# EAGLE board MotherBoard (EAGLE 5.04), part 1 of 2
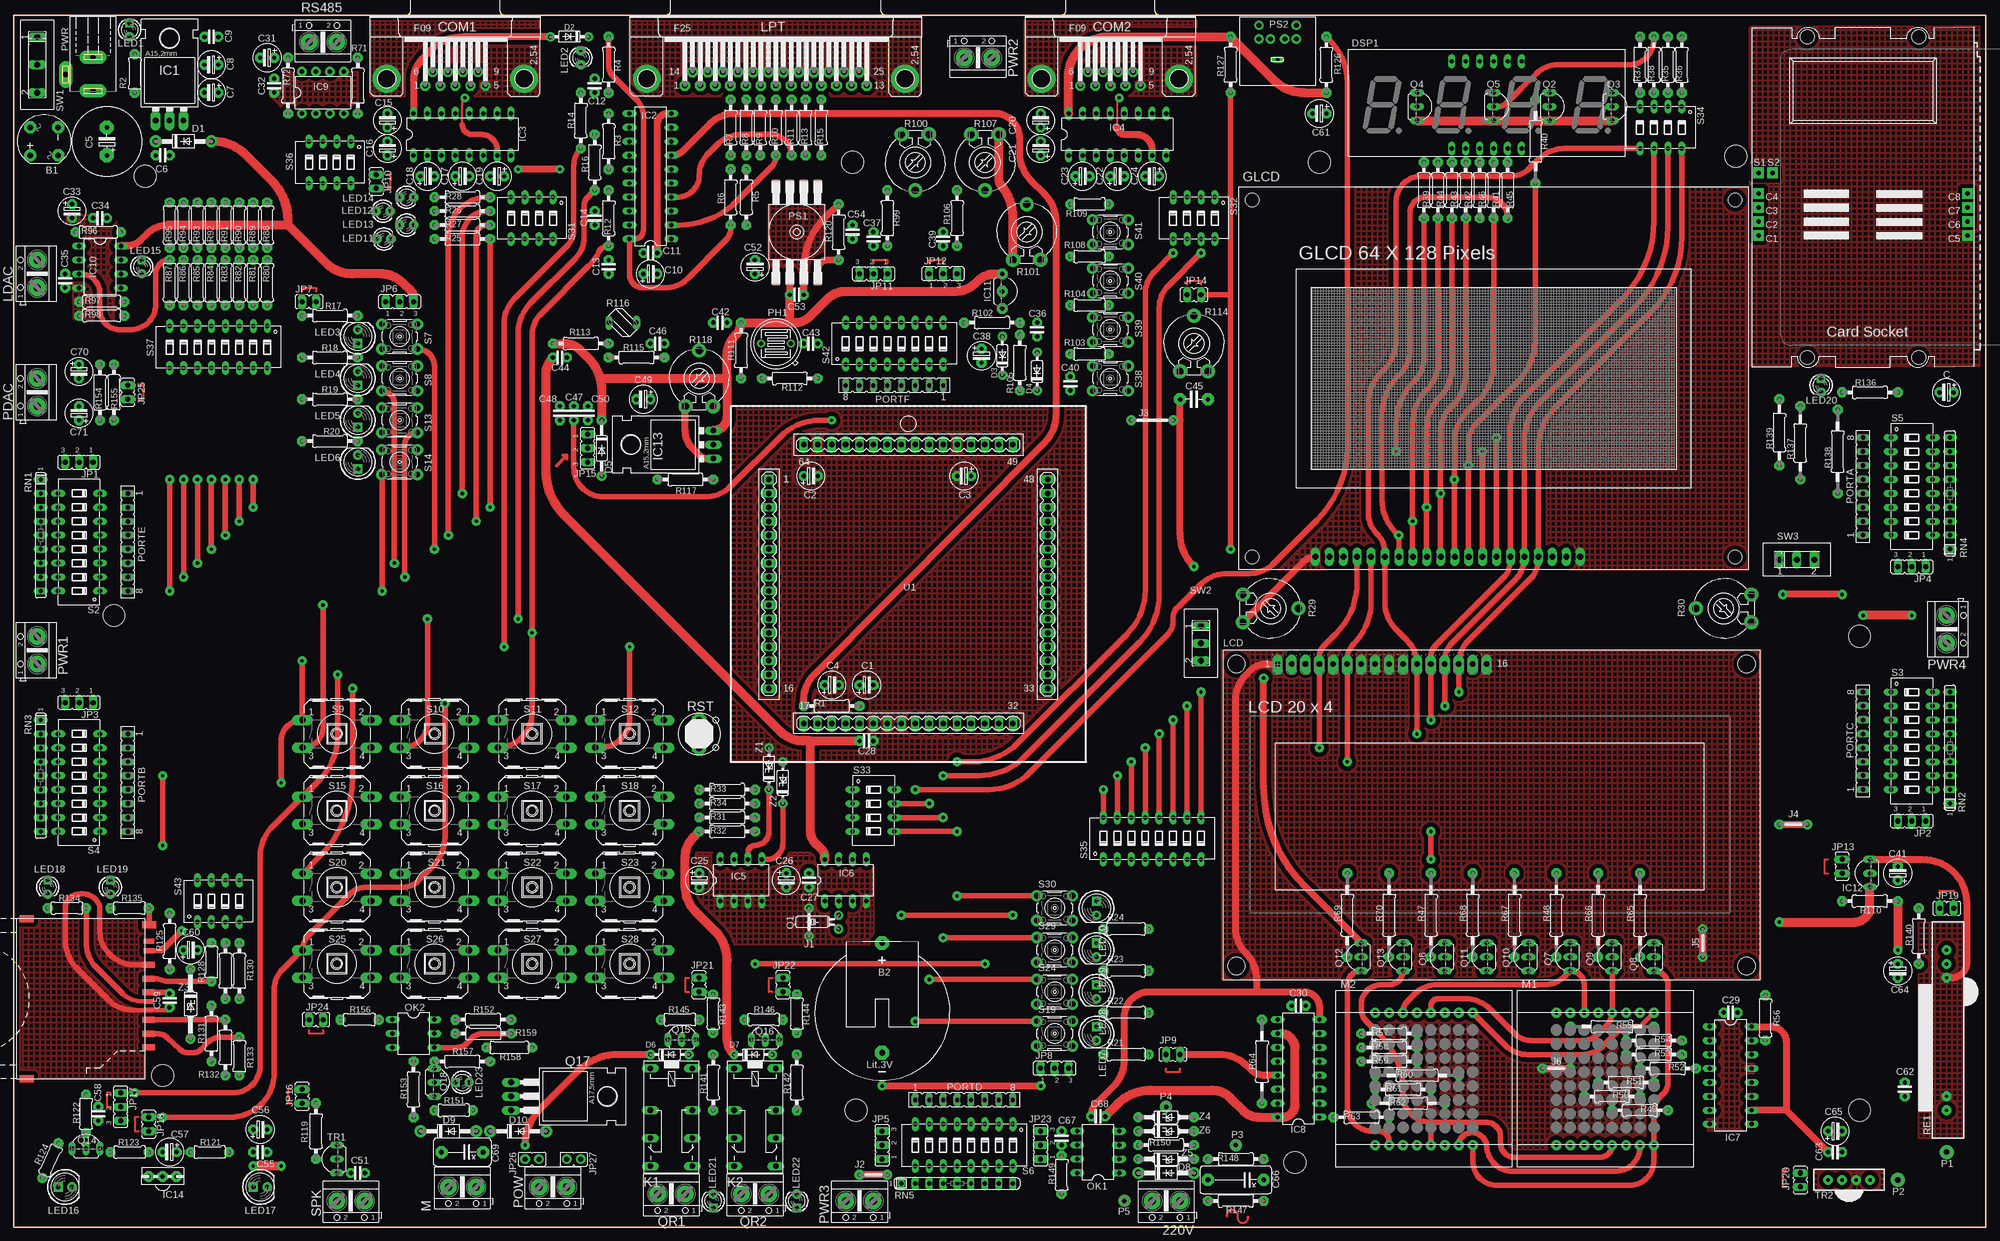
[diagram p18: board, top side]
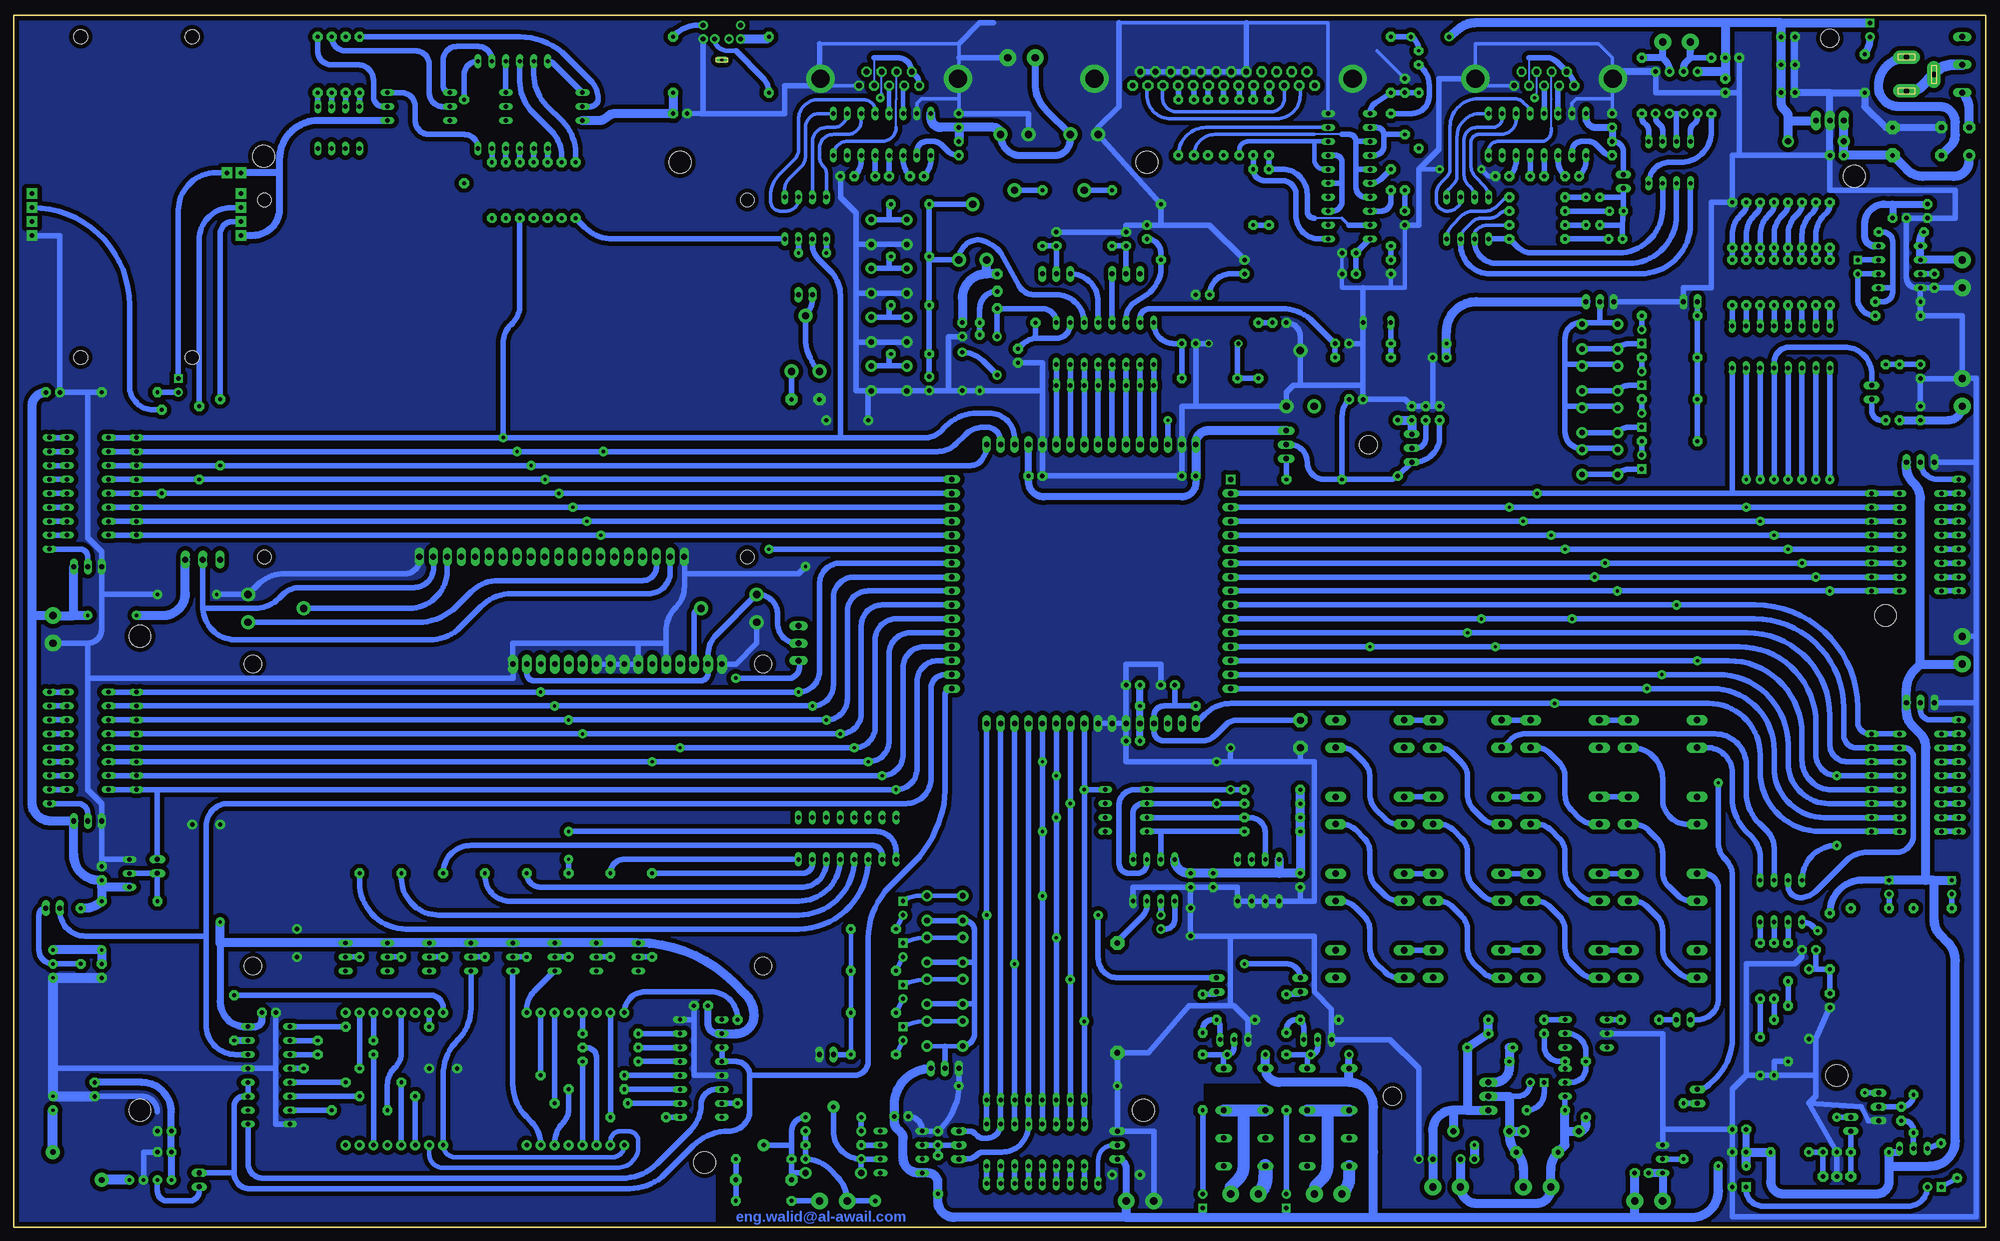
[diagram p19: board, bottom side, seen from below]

Size 359.41 x 220.82 mm. Coordinates in mm from the lower left corner, seen from the top.
Outline: 0.01,220.81 0.01,0.01
Outline: 0,0 359.41,0 359.41,220.82 0,220.82
Copper layers (1*16): Top 0.035mm / dielectric 1.5mm / Bottom 0.035mm
Design rules "default *": minimum track width 32mil, minimum drill 20mil, track to track 8mil, track to pad 8mil, pad to pad 8mil, via to via 8mil, smd to smd 8mil, copper to edge 20mil, drill to drill 8mil, minimum pad ring 10mil, minimum via ring 8mil, stop-mask expansion 4mil, vias tented up to drill 0mil, thermal gap 10mil
Holes 4 mm at 336.39,21.27 336.39,107.63 27.15,27.62 23.97,191.45 18.26,111.44 313.85,195.1 153.51,21.27 233.52,11.75 237.97,193.99 152.88,193.99

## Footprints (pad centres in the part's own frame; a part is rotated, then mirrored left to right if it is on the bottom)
AK500/2 = drill 1.321 pad 3.048 round: 1 -2.515,0; 2 2.515,0
RB1A = drill 1.016 pad 2.184 round: + -2.54,2.54 | drill 1.016 pad 2.184 octagon: - 2.54,-2.54; AC1 2.54,2.54; AC2 -2.54,-2.54
BATT = drill 1.016 pad 2.54 octagon: + 0,10.16; - 0,-9.842
ELC2.5 = drill 0.8 pad 1.778 octagon: 1 -1.27,0; 2 1.27,0
ELC5 = drill 0.8 pad 2.54 octagon: 1 -2.54,0; 2 2.54,0
CAP2.5 = drill 0.8 pad 1.778 octagon: 1 -1.27,0; 2 1.27,0
CAP5 = drill 0.8 pad 2.184 octagon: 1 -2.54,0; 2 2.54,0
CXXC10BS = drill 0.9 pad 2.184 octagon: 1 -5.08,0; 2 5.08,0
CXXC7BS = drill 0.9 pad 2.184 octagon: 1 -5.08,0; 2 2.54,0
F09HP = drill 1.016 pad 1.778 octagon: 1 -5.486,-1.27; 2 -2.743,-1.27; 3 0,-1.27; 4 2.743,-1.27; 5 5.486,-1.27; 6 -4.115,1.27; 7 -1.372,1.27; 8 1.372,1.27; 9 4.115,1.27 | drill 3.302 pad 5.08 round: G1 -12.522,0; G2 12.522,0
DO41-10 = drill 1.118 pad 2.184 round: A 5.08,0; C -5.08,0
DO35-7 = drill 0.813 pad 1.676 round: A 3.175,0; C -3.81,0
DO35-10 = drill 0.813 pad 1.778 round: A 5.08,0; C -5.08,0
DISPLAY-Q0.56 = drill 0.813 long: 1 -6.35,-7.62; 2 -3.81,-7.62; 3 -1.27,-7.62; 4 1.27,-7.62; 5 3.81,-7.62; 6 6.35,-7.62; 7 6.35,8.255; 8 3.81,8.255; 9 1.27,8.255; 10 -1.27,8.255; 11 -3.81,8.255; 12 -6.35,8.255
LCD128X64 = drill 1.1 pad 1.676 long: 1 15.76,-32.5; 2 13.22,-32.5; 3 10.68,-32.5; 4 8.14,-32.5; 5 5.6,-32.5; 6 3.06,-32.5; 7 0.52,-32.5; 8 -2.02,-32.5; 9 -4.56,-32.5; 10 -7.1,-32.5; 11 -9.64,-32.5; 12 -12.18,-32.5; 13 -14.72,-32.5; 14 -17.26,-32.5; 15 -19.8,-32.5; 16 -22.34,-32.5; 17 -24.88,-32.5; 18 -27.42,-32.5; 19 -29.96,-32.5; 20 -32.5,-32.5 | hole 2.5: -44,-32.5; 44,-32.5; -44,32.5; 44,32.5
78XXL = drill 1.016 pad 1.778 long: GND 0,-3.81; IN -2.54,-3.81; OUT 2.54,-3.81 | hole 3.302: 0,11.176
DIL20 = drill 0.813 long: 1 -11.43,-3.81; 2 -8.89,-3.81; 3 -6.35,-3.81; 4 -3.81,-3.81; 5 -1.27,-3.81; 6 1.27,-3.81; 7 3.81,-3.81; 8 6.35,-3.81; 9 8.89,-3.81; 10 11.43,-3.81; 11 11.43,3.81; 12 8.89,3.81; 13 6.35,3.81; 14 3.81,3.81; 15 1.27,3.81; 16 -1.27,3.81; 17 -3.81,3.81; 18 -6.35,3.81; 19 -8.89,3.81; 20 -11.43,3.81
DIL16L = drill 0.813 long: 1 -8.89,-3.81; 2 -6.35,-3.81; 3 -3.81,-3.81; 4 -1.27,-3.81; 5 1.27,-3.81; 6 3.81,-3.81; 7 6.35,-3.81; 8 8.89,-3.81; 9 8.89,3.81; 10 6.35,3.81; 11 3.81,3.81; 12 1.27,3.81; 13 -1.27,3.81; 14 -3.81,3.81; 15 -6.35,3.81; 16 -8.89,3.81
DIL8L = drill 0.813 long: 1 -3.81,-3.81; 2 -1.27,-3.81; 3 1.27,-3.81; 4 3.81,-3.81; 5 3.81,3.81; 6 1.27,3.81; 7 -1.27,3.81; 8 -3.81,3.81
DIL8R = drill 0.813 pad 1.778 round: 1 -3.81,-3.81; 2 -1.27,-3.81; 3 1.27,-3.81; 4 3.81,-3.81; 5 3.81,3.81; 6 1.27,3.81; 7 -1.27,3.81; 8 -3.81,3.81
DIL08 = drill 0.813 long: 1 -3.81,-3.81; 2 -1.27,-3.81; 3 1.27,-3.81; 4 3.81,-3.81; 5 3.81,3.81; 6 1.27,3.81; 7 -1.27,3.81; 8 -3.81,3.81
LM35 = drill 0.813 pad 1.93 octagon: 1 3.175,0; 2 0,0; 3 -3.175,0
TO92L = drill 0.813 long: 1 2.54,0; 2 0,0; 3 -2.54,0
317TL = drill 1.016 long: 1 -2.54,-3.81; 2 0,-3.81; 3 2.54,-3.81 | hole 3.302: 0,11.176
IR-RECEIVER = drill 0.813 pad 1.93 octagon: GND 0,0; OUT 2.54,0; VCC -2.54,0
05 = drill 0.813 pad 1.6 octagon: 1 -2.54,0; 2 2.54,0
05' = drill 0.8 pad 1.778 round: 1 -2.54,0; 2 2.54,0
07 = drill 0.8 pad 1.778 round: 1 -3.81,0; 2 3.81,0
JP2 = drill 0.914 long: 1 -2.54,0; 2 0,0; 3 2.54,0
JP1Y = drill 0.914 long: 1 0,-1.27; 2 0,1.27
JP1 = drill 0.914 pad 1.778 round: 1 0,-1.27; 2 0,1.27
351 = drill 1.016 long: 1 -3.81,-3.81; 16 -3.81,3.81; O1 8.89,-3.81; O2 8.89,3.81; P1 3.81,-3.81; P2 3.81,3.81; S1 13.97,-3.81; S2 13.97,3.81
LCD20X4 = drill 1.016 pad 1.778 long: 1 -38.108,27.947; 2 -35.568,27.947; 3 -33.028,27.947; 4 -30.488,27.947; 5 -27.948,27.947; 6 -25.408,27.947; 7 -22.868,27.947; 8 -20.328,27.947; 9 -17.788,27.947; 10 -15.248,27.947; 11 -12.708,27.947; 12 -10.168,27.947; 13 -7.628,27.947; 14 -5.088,27.947; 15 -2.548,27.947; 16 -0.008,27.947 | hole 3.2: -45.601,27.94; -45.601,-27.067; 47.387,-27.067; 47.387,27.94
LED3MM = drill 0.8 pad 1.524 square: A -1.27,0 | drill 0.8 pad 1.676 round: K 1.27,0
LED3MM' = drill 0.61 pad 1.676 octagon: A -1.27,0; K 1.27,0
LED5MM = drill 0.8 pad 1.676 square: A -1.27,0 | drill 0.8 pad 1.676 round: K 1.27,0
F25HP = drill 1.016 pad 1.93 octagon: 1 -16.561,-1.27; 2 -13.792,-1.27; 3 -11.049,-1.27; 4 -8.28,-1.27; 5 -5.512,-1.27; 6 -2.769,-1.27; 7 0,-1.27; 8 2.769,-1.27; 9 5.512,-1.27; 10 8.28,-1.27; 11 11.049,-1.27; 12 13.792,-1.27; 13 16.561,-1.27; 14 -15.189,1.27; 15 -12.421,1.27; 16 -9.652,1.27; 17 -6.909,1.27; 18 -4.14,1.27; 19 -1.372,1.27; 20 1.372,1.27; 21 4.14,1.27; 22 6.909,1.27; 23 9.652,1.27; 24 12.421,1.27; 25 15.189,1.27 | drill 3.302 pad 5.08 round: G1 -23.52,0; G2 23.52,0
8X8MATRIX-3MM = drill 0.8 pad 1.8 round: 1 -8.89,-11.43; 2 -6.35,-11.43; 3 -3.81,-11.43; 4 -1.27,-11.43; 5 1.27,-11.43; 6 3.81,-11.43; 7 6.35,-11.43; 8 8.89,-11.43; 9 8.89,12.7; 10 6.35,12.7; 11 3.81,12.7; 12 1.27,12.7; 13 -1.27,12.7; 14 -3.81,12.7; 15 -6.35,12.7; 16 -8.89,12.7
DIL06 = drill 0.813 long: 1 -2.54,-3.81; 2 0,-3.81; 3 2.54,-3.81; 4 2.54,3.81; 5 0,3.81; 6 -2.54,3.81
PAD1 = drill 1.016 pad 2.54 round: 1 0,0
PAD0 = drill 0.813 pad 2.184 round: 1 0,0
TO-5_V10 = drill 0.8 pad 1.4 round: 1 -2.7,0; 2 2.7,0
FE08 = drill 0.813 long: 1 -8.89,0; 2 -6.35,0; 3 -3.81,0; 4 -1.27,0; 5 1.27,0; 6 3.81,0; 7 6.35,0; 8 8.89,0
MPXAZ6115A = smd 2.54 x 1.27: 1 8.414,-3.81; 2 8.414,-1.27; 3 8.414,1.27; 4 8.414,3.81; 5 -8.255,3.81; 6 -8.255,1.27; 7 -8.255,-1.27; 8 -8.255,-3.81
PS2-CON = drill 0.9 pad 1.676 round: 1 1.3,8.5; 2 -1.3,8.5; 3 3.4,8.5; 4 -3.4,8.5; 5 3.4,11; 6 -3.4,11 | drill 0.7 long: M 0,4.7
PW = drill 1 pad 2.5 long: + 0,8.57; - 0,2.42; C 5,5.57
TC26 = drill 0.813 pad 1.676 round: 1 -1.27,-5.08; 2 1.27,-5.08
TO220 = drill 1.118 long: 1 -2.54,-6.35; 2 0,-6.35; 3 2.54,-6.35 | hole 3.302: 0,11.176
R-10 = drill 0.7 pad 1.778 octagon: 1 -5.08,0; 2 5.08,0
R-7 = drill 0.7 pad 1.778 octagon: 1 -3.175,0; 2 3.81,0
R-8 = drill 0.7 pad 1.778 octagon: 1 -3.81,0; 2 4.445,0
POT = drill 1.321 pad 2.54 round: A -2.54,-5.08; E 2.54,-5.08; S 0,5.08
R-15 = drill 0.7 pad 1.778 octagon: 1 -7.62,0; 2 7.62,0
R-13 = drill 0.7 pad 1.778 octagon: 1 -6.985,0; 2 6.35,0
B57164 = drill 0.813 long: 1 -2.54,0; 2 2.54,0
R-12 = drill 0.7 pad 1.778 octagon: 1 -5.715,0; 2 6.35,0
GDRX5 = drill 0.6 pad 1.778 round: 1 -12.7,0; 2 -10.16,0; 3 11.43,0; 4 13.97,0; 5 16.51,0
SIL9 = drill 0.813 long: 1 -10.16,0; 2 -7.62,0; 3 -5.08,0; 4 -2.54,0; 5 0,0; 6 2.54,0; 7 5.08,0; 8 7.62,0; 9 10.16,0
SW = drill 1.27 pad 2.54 octagon: 1 -3.785,0; 2 1.245,0
DIP08YL = drill 0.813 long: 1 -8.89,-3.81; 2 -6.35,-3.81; 3 -3.81,-3.81; 4 -1.27,-3.81; 5 1.27,-3.81; 6 3.81,-3.81; 7 6.35,-3.81; 8 8.89,-3.81; 9 8.89,3.81; 10 6.35,3.81; 11 3.81,3.81; 12 1.27,3.81; 13 -1.27,3.81; 14 -3.81,3.81; 15 -6.35,3.81; 16 -8.89,3.81
B3F-10XX = drill 1.016 pad 2.032 round: 1 -3.251,2.261; 2 3.251,2.261; 3 -3.251,-2.261; 4 3.251,-2.261
B3F-40XX = drill 1.194 pad 1.93 long: 1 -6.248,2.489; 2 6.248,2.489; 3 -6.248,-2.489; 4 6.248,-2.489
DIP04YL = drill 0.813 long: 1 -3.81,-3.81; 2 -1.27,-3.81; 3 1.27,-3.81; 4 3.81,-3.81; 5 3.81,3.81; 6 1.27,3.81; 7 -1.27,3.81; 8 -3.81,3.81
MMC-SD-CARD-P = smd 2.184 x 1.067: 1 17.817,-7.619; 2 17.817,-5.119; 4 17.817,-0.119; 5 17.817,2.381; 6 17.817,4.921; 9 17.817,-10.119 | smd 1.676 x 0.813: 3 17.78,-3.334; S2 17.78,-1.746 | smd 1.93 x 0.965: 7 17.817,7.461; 8 17.817,9.207 | smd 2.54 x 1.27: F1 -4.445,13.335; F2 -4.445,-15.875; S1 17.897,12.224
SWITCH = drill 1.118 long: 1 -5.08,0; 2 5.08,0; P 0,0
ON_OFF = drill 1.118 long: 1 -3.175,0; 2 3.175,0; P 0,0
GDTX6 = drill 0.6 pad 1.778 round: 1 3.81,0; 2 1.27,0; 3 -1.27,0; 4 -3.81,0
HEADER64PIN = drill 1.016 pad 1.778 square: 1 -25.4,19.685 | drill 1.016 long: 2 -25.4,17.145; 3 -25.4,14.605; 4 -25.4,12.065; 5 -25.4,9.525; 6 -25.4,6.985; 7 -25.4,4.445; 8 -25.4,1.905; 9 -25.4,-0.635; 10 -25.4,-3.175; 11 -25.4,-5.715; 12 -25.4,-8.255; 13 -25.4,-10.795; 14 -25.4,-13.335; 15 -25.4,-15.875; 16 -25.4,-18.415; 17 -19.05,-24.765; 18 -16.51,-24.765; 19 -13.97,-24.765; 20 -11.43,-24.765; 21 -8.89,-24.765; 22 -6.35,-24.765; 23 -3.81,-24.765; 24 -1.27,-24.765; 25 1.27,-24.765; 26 3.81,-24.765; 27 6.35,-24.765; 28 8.89,-24.765; 29 11.43,-24.765; 30 13.97,-24.765; 31 16.51,-24.765; 32 19.05,-24.765; 33 25.4,-18.415; 34 25.4,-15.875; 35 25.4,-13.335; 36 25.4,-10.795; 37 25.4,-8.255; 38 25.4,-5.715; 39 25.4,-3.175; 40 25.4,-0.635; 41 25.4,1.905; 42 25.4,4.445; 43 25.4,6.985; 44 25.4,9.525; 45 25.4,12.065; 46 25.4,14.605; 47 25.4,17.145; 48 25.4,19.685; 49 19.05,26.035; 50 16.51,26.035; 51 13.97,26.035; 52 11.43,26.035; 53 8.89,26.035; 54 6.35,26.035; 55 3.81,26.035; 56 1.27,26.035; 57 -1.27,26.035; 58 -3.81,26.035; 59 -6.35,26.035; 60 -8.89,26.035; 61 -11.43,26.035; 62 -13.97,26.035; 63 -16.51,26.035; 64 -19.05,26.035
CARDSOCKET = drill 0.813 pad 1.93 square: CLK -19.05,-1.905; GND 19.05,-6.985; I/O 19.05,-1.905; PIN4 -19.05,0.635; PIN6 19.05,-4.445; PIN8 19.05,0.635; RST -19.05,-4.445; SW1 -19.05,4.445; SW2 -16.51,4.445; VCC -19.05,-6.985 | hole 2.54: 10.16,29.21; -10.16,29.21; 10.16,-29.21; -10.16,-29.21
DO35-7B = drill 0.8 pad 1.676 round: A 3.81,0; C -3.81,0
SOD120 = drill 0.8 pad 1.778 round: A 6.35,0; C -6.35,0
SOD81 = drill 0.8 pad 1.778 round: A 5.08,0; C -5.08,0

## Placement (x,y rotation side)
220V  [AK500/2]  210.03,4.76 180 top
B1  [RB1A]  5.56,197.8 90 top
B2  [BATT]  158.27,41.59 0 top
C  1uF  [ELC2.5]  352.27,152.08 180 top
C1  1uF  [ELC2.5]  155.42,98.74 0 top
C2  1uF  [ELC2.5]  145.26,136.84 0 top
C3  1uF  [ELC2.5]  173.2,136.84 180 top
C4  1uF  [ELC2.5]  149.07,98.74 0 top
C5  1000uF  [ELC5]  16.99,197.8 90 top
C6  100nF  [CAP2.5]  27.15,195.26 180 top
C7  100uF  [ELC2.5]  36.04,206.69 180 top
C8  10uF  [ELC2.5]  36.04,211.77 180 top
C9  100nF  [CAP2.5]  36.04,216.85 0 top
C10  100nF  [CAP2.5]  116.05,177.48 180 top
C11  1uF  [ELC2.5]  116.05,173.67 0 top
C12  100pF  [CAP2.5]  105.89,207.96 270 top
C13  100pF  [CAP2.5]  108.43,174.94 90 top
C14  100pF  [CAP2.5]  105.89,183.83 90 top
C15  1uF  [ELC2.5]  68.1,201.61 90 top
C16  1uF  [ELC2.5]  68.1,196.53 90 top
C17  1uF  [ELC2.5]  81.76,191.45 0 top
C18  1uF  [ELC2.5]  75.41,191.45 0 top
C19  1uF  [ELC2.5]  88.11,191.45 180 top
C20  1uF  [ELC2.5]  187.17,201.61 90 top
C21  1uF  [ELC2.5]  187.17,196.53 90 top
C22  1uF  [ELC2.5]  201.14,191.45 0 top
C23  1uF  [ELC2.5]  194.79,191.45 0 top
C24  1uF  [ELC2.5]  207.49,191.45 180 top
C25  1uF  [ELC2.5]  124.94,63.18 270 top
C26  100nF  [CAP2.5]  144.94,63.18 90 top
C27  1uF  [ELC2.5]  140.81,63.18 270 top
C28  100nF  [CAP2.5]  155.42,88.58 0 top
C29  100nF  [CAP2.5]  312.9,39.05 0 top
C30  100nF  [CAP2.5]  234.16,40.32 180 top
C31  1uF  [ELC2.5]  46.2,213.04 180 top
C32  100nF  [CAP2.5]  47.47,207.96 90 top
C33  1uF  [ELC2.5]  10.64,185.1 270 top
C34  100nF  [CAP2.5]  15.72,183.83 0 top
C35  100pF  [CAP2.5]  9.37,172.4 90 top
C36  100nF  [CAP2.5]  186.53,163.51 270 top
C37  100nF  [CAP2.5]  156.69,180.02 270 top
C38  1uF  [ELC2.5]  176.37,158.75 270 top
C39  100nF  [CAP2.5]  169.39,180.02 270 top
C40  100nF  [CAP2.5]  192.56,153.67 90 top
C41  1uF  [ELC2.5]  343.38,64.45 90 top
C42  100nF  [CAP2.5]  128.75,164.78 0 top
C43  100nF  [CAP2.5]  145.26,160.97 0 top
C44  100nF  [CAP2.5]  99.54,158.43 180 top
C45  100nF  [CAP5]  215.11,150.81 0 top
C46  100nF  [CAP2.5]  117.32,160.97 0 top
C47  100nF  [CAP2.5]  102.08,148.27 270 top
C48  100nF  [CAP2.5]  99.54,148.27 270 top
C49  1uF  [ELC2.5]  114.78,150.81 180 top
C50  100nF  [CAP2.5]  104.62,148.27 270 top
C51  100nF  [CAP2.5]  62.71,9.84 0 top
C52  1uF  [ELC2.5]  135.1,174.94 90 top
C53  100nF  [CAP2.5]  142.72,169.86 180 top
C54  47nF  [CAP2.5]  152.88,181.29 270 top
C55  100nF  [CAP2.5]  44.93,13.65 180 top
C56  10uF  [ELC2.5]  44.93,17.78 0 top
C57  4.7uF  [ELC2.5]  28.42,13.65 180 top
C58  10nF  [CAP2.5]  15.4,20.64 270 top
C59  100nF  [CAP2.5]  28.42,41.28 90 top
C60  1uF  [ELC2.5]  32.23,50.48 0 top
C61  1uF  [ELC2.5]  237.97,202.88 180 top
C62  100nF  [CAP2.5]  344.65,25.08 270 top
C63  100nF  [CAP2.5]  331.95,13.65 0 top
C64  4.7uF  [ELC2.5]  343.38,46.67 270 top
C65  4.7uF  [ELC2.5]  331.95,17.46 0 top
C66  0.47uF/250V  [CXXC10BS]  222.73,8.57 180 top
C67  27pF  [CAP2.5]  190.98,16.19 270 top
C68  100nF  [CAP2.5]  197.64,20.16 180 top
C69  100nF  [CXXC7BS]  80.49,13.65 180 top
C70  ?  [ELC2.5]  11.91,155.89 270 top
C71  ?  [ELC2.5]  11.91,148.27 90 top
COM1  [F09HP]  80.49,209.23 0 top
COM2  [F09HP]  199.87,209.23 0 top
D1  1N4004  [DO41-10]  30.96,197.8 0 top
D2  1N4148-7  [DO35-7]  100.97,216.85 180 top
D3  1N4148  [DO35-7]  180.18,159.07 90 top
D4  1N4148  [DO35-7]  186.53,156.21 90 top
D5  1N4148  [DO35-10]  107.16,141.92 270 top
D6  1N4148-7  [DO35-7]  119.86,31.43 0 top
D7  1N4148-7  [DO35-7]  135.1,31.43 0 top
D8  1N4004  [DO41-10]  210.03,9.84 0 top
D9  1N4004  [DO41-10]  79.22,17.46 0 top
D10  1N4004  [DO41-10]  91.92,17.46 0 top
DSP1  [DISPLAY-Q0.56]  268.45,204.15 0 top
GLCD  [LCD128X64]  269.72,154.62 0 top
IC1  7805  [78XXL]  28.42,205.42 0 top
IC2  74LS244N  [DIL20]  116.05,191.45 90 top
IC3  MAX232  [DIL16L]  81.76,199.07 0 top
IC4  MAX232  [DIL16L]  201.14,199.07 0 top
IC5  24C512  [DIL8L]  132.56,63.18 0 top
IC6  DS1307  [DIL8L]  151.61,63.18 0 top
IC7  74HC595  [DIL16L]  312.9,27.62 270 top
IC8  74HC595  [DIL16L]  234.16,28.89 90 top
IC9  MAX484  [DIL8R]  56.36,206.69 0 top
IC10  LM358N  [DIL08]  15.72,174.94 270 top
IC11  LM35  [LM35]  180.18,170.5 90 top
IC12  DS1820  [TO92L]  338.3,64.45 90 top
IC13  LM7317  [317TL]  123.67,142.56 90 top
IC14  [IR-RECEIVER]  27.15,9.21 180 top
J1  J5MM  [05]  144.94,55.56 90 top
J2  [05']  156.69,9.53 0 top
J3  [07]  207.49,147 0 top
J4  [05']  324.33,73.34 0 top
J5  [05']  307.82,51.75 90 top
J6  [05']  281.15,28.89 0 top
JP1  [JP2]  11.91,139.38 180 top
JP2  [JP2]  345.92,73.98 180 top
JP3  [JP2]  11.91,95.57 180 top
JP4  [JP2]  345.92,120.33 180 top
JP5  [JP2]  158.27,14.92 90 top
JP6  [JP2]  70.33,168.59 0 top
JP7  [JP1Y]  53.82,168.59 270 top
JP8  [JP2]  189.71,28.89 0 top
JP9  [JP1Y]  211.3,31.43 270 top
JP10  [JP1Y]  66.04,190.5 0 top
JP11  [JP2]  156.69,173.67 180 top
JP12  [JP2]  169.39,173.67 0 top
JP13  [JP1Y]  333.22,65.72 0 top
JP14  [JP1Y]  215.11,169.86 270 top
JP15  [JP2]  104.62,141.92 270 top
JP16  [JP1Y]  52.55,23.81 180 top
JP17  [JP2]  19.53,21.91 270 top
JP18  [JP1Y]  24.61,18.73 0 top
JP19  [JP1Y]  352.27,58.1 90 top
JP20  [JP1Y]  325.6,8.57 0 top
JP21  [JP1Y]  124.94,44.13 180 top
JP22  [JP1Y]  140.18,44.13 180 top
JP23  [JP2]  187.17,14.92 90 top
JP24  [JP1Y]  55.09,37.78 270 top
JP25  [JP1Y]  20.8,152.08 180 top
JP26  [JP1]  94.46,12.38 90 top
JP27  [JP1]  102.08,12.38 90 top
K1  351  [351]  119.86,25.08 270 top
K2  351  [351]  135.1,25.08 270 top
LCD  [LCD20X4]  268.45,74.61 0 top
LDAC  [AK500/2]  4.29,173.67 90 top
LED1  [LED3MM]  21.11,218.12 270 top
LED2  [LED3MM']  103.35,213.04 270 top
LED3  [LED5MM]  62.71,162.24 90 top
LED4  [LED5MM]  62.71,154.62 90 top
LED5  [LED5MM]  62.71,147 90 top
LED6  [LED5MM]  62.71,139.38 90 top
LED7  [LED5MM]  197.33,35.24 270 top
LED8  [LED5MM]  197.33,42.86 270 top
LED9  [LED5MM]  197.33,50.48 270 top
LED10  [LED5MM]  197.33,58.1 270 top
LED11  [LED3MM']  67.47,180.02 0 top
LED12  [LED3MM']  67.31,185.1 0 top
LED13  [LED3MM']  71.6,182.56 0 top
LED14  [LED3MM']  71.6,187.64 0 top
LED15  [LED3MM]  23.34,174.94 270 top
LED16  [LED5MM]  9.37,7.3 0 top
LED17  [LED5MM]  44.93,7.3 0 top
LED18  [LED3MM]  6.19,61.91 270 top
LED19  [LED3MM]  17.62,61.91 270 top
LED20  [LED3MM]  329.41,153.35 270 top
LED21  [LED3MM]  127.48,4.76 90 top
LED22  [LED3MM]  142.72,4.76 90 top
LED23  [LED3MM]  81.76,26.35 0 top
LPT  [F25HP]  138.91,209.23 0 top
M  [AK500/2]  81.76,7.3 180 top
M1  [8X8MATRIX-3MM]  290.04,26.35 0 top
M2  [8X8MATRIX-3MM]  257.02,26.35 0 top
OK1  6N137  [DIL08]  197.64,13.65 90 top
OK2  4N35  [DIL06]  72.87,35.24 270 top
P1  [PAD1]  352.27,13.65 180 top
P2  [PAD1]  343.38,8.57 180 top
P3  [PAD0]  222.73,14.92 0 top
P4  [PAD0]  210.03,21.91 0 top
P5  [PAD0]  202.41,4.76 0 top
PDAC  [AK500/2]  4.29,152.08 90 top
PH1  100K  [TO-5_V10]  138.91,160.97 0 top
PORTA  [FE08]  337.03,134.94 90 top
PORTB  [FE08]  20.8,80.96 270 top
PORTC  [FE08]  337.03,88.58 90 top
PORTD  [FE08]  173.2,23.18 0 top
PORTE  [FE08]  20.8,124.78 270 top
PORTF  [FE08]  160.5,153.35 180 top
POW  [AK500/2]  98.27,7.3 180 top
PS1  [MPXAZ6115A]  142.72,181.29 270 top
PS2  [PS2-CON]  230.35,207.96 0 top
PWR  [PW]  14.45,215.58 180 top
PWR1  [AK500/2]  4.29,105.09 90 top
PWR2  [AK500/2]  175.74,213.04 0 top
PWR3  [AK500/2]  154.15,4.76 180 top
PWR4  [AK500/2]  352.27,108.9 270 top
Q1  32KHZ  [TC26]  145.26,55.56 90 top
Q2  BC327  [TO92L]  279.88,204.15 270 top
Q3  BC327  [TO92L]  291.31,204.15 270 top
Q4  BC327  [TO92L]  255.75,204.15 270 top
Q5  BC327  [TO92L]  269.72,204.15 270 top
Q6  [TO92L]  260.83,49.21 90 top
Q7  [TO92L]  283.69,49.21 90 top
Q8  [TO92L]  298.93,49.21 90 top
Q9  [TO92L]  291.31,49.21 90 top
Q10  [TO92L]  276.07,49.21 90 top
Q11  [TO92L]  268.45,49.21 90 top
Q12  [TO92L]  245.59,49.21 90 top
Q13  [TO92L]  253.21,49.21 90 top
Q14  BC327  [TO92L]  13.18,14.29 0 top
Q15  [TO92L]  121.76,34.13 0 top
Q16  [TO92L]  137,34.13 0 top
Q17  IRF540  [TO220]  97,23.81 270 top
Q18  [TO92L]  76.68,26.35 270 top
QR1  [AK500/2]  119.86,6.03 180 top
QR2  [AK500/2]  135.1,6.03 180 top
R1  10K  [R-10]  149.07,94.93 180 top
R2  300  [R-7]  22.07,209.87 90 top
R3  300  [R-10]  108.43,197.8 90 top
R4  100K  [R-10]  108.43,211.77 90 top
R5  100K  [R-10]  133.51,187.64 270 top
R6  100K  [R-10]  130.65,187.64 270 top
R7  300  [R-10]  130.65,200.34 270 top
R8  300  [R-10]  133.51,200.34 270 top
R9  300  [R-10]  136.05,200.34 270 top
R10  300  [R-10]  138.91,200.34 270 top
R11  300  [R-10]  141.76,200.34 270 top
R12  300  [R-10]  108.43,183.83 270 top
R13  300  [R-10]  144.3,200.34 270 top
R14  300  [R-10]  103.35,201.61 270 top
R15  150  [R-10]  147.16,200.34 270 top
R16  300  [R-10]  105.89,193.99 270 top
R17  300  [R-10]  57.63,166.05 180 top
R18  300  [R-10]  57.63,158.43 180 top
R19  300  [R-10]  57.63,150.81 180 top
R20  300  [R-10]  57.63,143.19 180 top
R21  300  [R-8]  202.41,31.43 0 top
R22  300  [R-8]  202.41,39.05 0 top
R23  300  [R-8]  202.41,46.67 0 top
R24  300  [R-8]  202.41,54.29 0 top
R25  560  [R-10]  81.76,180.02 180 top
R26  560  [R-10]  81.76,185.1 180 top
R27  560  [R-10]  81.76,182.56 180 top
R28  560  [R-10]  81.76,187.64 180 top
R29  10K  [POT]  229.08,112.71 270 top
R30  10K  [POT]  311.63,112.71 90 top
R31  10K  [R-10]  130.02,74.61 180 top
R32  4K7  [R-10]  130.02,72.07 180 top
R33  1K5  [R-10]  130.02,79.69 180 top
R34  1K5  [R-10]  130.02,77.15 180 top
R35  4K7  [R-10]  301.47,211.77 270 top
R36  4K7  [R-10]  304.01,211.77 270 top
R37  4K7  [R-10]  296.39,211.77 270 top
R38  4K7  [R-10]  298.93,211.77 270 top
R39  150  [R-10]  257.02,188.91 90 top
R40  150  [R-15]  277.34,197.8 90 top
R41  150  [R-10]  269.72,188.91 90 top
R42  150  [R-10]  264.64,188.91 90 top
R43  150  [R-10]  262.1,188.91 90 top
R44  150  [R-10]  259.56,188.91 90 top
R45  150  [R-10]  272.26,188.91 90 top
R46  150  [R-10]  267.18,188.91 90 top
R47  2K2  [R-15]  258.29,56.83 270 top
R48  2K2  [R-15]  281.15,56.83 270 top
R49  10  [R-10]  296.39,21.27 0 top
R50  10  [R-10]  291.31,23.81 0 top
R51  10  [R-10]  293.85,26.35 0 top
R52  10  [R-10]  301.47,28.89 0 top
R53  10  [R-10]  298.93,31.43 0 top
R54  10  [R-10]  298.93,33.97 0 top
R55  10  [R-15]  291.31,36.51 0 top
R56  10  [R-8]  319.25,38.42 270 top
R57  10  [R-10]  250.67,35.24 180 top
R58  10  [R-10]  250.67,32.7 180 top
R59  10  [R-10]  250.67,30.16 180 top
R60  10  [R-15]  255.75,27.62 180 top
R61  10  [R-10]  253.21,25.08 180 top
R62  10  [R-13]  253.84,22.54 180 top
R63  10  [R-10]  245.59,20 180 top
R64  10  [R-15]  227.49,30.16 270 top
R65  2K2  [R-15]  296.39,56.83 270 top
R66  2K2  [R-15]  288.77,56.83 270 top
R67  2K2  [R-15]  273.53,56.83 270 top
R68  2K2  [R-15]  265.91,56.83 270 top
R69  2K2  [R-15]  243.05,56.83 270 top
R70  2K2  [R-15]  250.67,56.83 270 top
R71  120  [R-10]  62.71,207.96 90 top
R72  0  [R-10]  50.01,207.96 90 top
R80  20K  [R-8]  46.2,172.4 270 top
R81  20K  [R-8]  43.66,172.4 270 top
R82  20K  [R-8]  41.12,172.4 270 top
R83  20K  [R-8]  38.58,172.4 270 top
R84  20K  [R-8]  36.04,172.4 270 top
R85  20K  [R-8]  33.5,172.4 270 top
R86  20K  [R-8]  30.96,172.4 270 top
R87  20K  [R-8]  28.42,172.4 270 top
R88  20K  [R-8]  46.2,182.88 270 top
R89  10K  [R-8]  43.66,182.88 270 top
R90  10K  [R-8]  41.12,182.88 270 top
R91  10K  [R-8]  38.58,182.88 270 top
R92  10K  [R-8]  36.04,182.88 270 top
R93  10K  [R-8]  33.5,182.88 270 top
R94  10K  [R-8]  30.96,182.88 270 top
R95  10K  [R-8]  28.42,182.88 270 top
R96  20K  [R-8]  15.72,181.29 180 top
R97  20K  [R-8]  15.72,168.59 0 top
R98  20K  [R-8]  15.72,166.05 0 top
R99  1K  [R-10]  159.23,183.83 90 top
R100  10K  [POT]  164.31,193.99 180 top
R101  10K  [POT]  184.63,181.29 0 top
R102  100  [R-10]  178.28,164.78 180 top
R103  1K  [R-7]  196.37,159.07 180 top
R104  2K2  [R-7]  196.37,167.96 180 top
R105  18K  [R-10]  183.36,157.48 270 top
R106  1K  [R-10]  171.93,183.83 90 top
R107  10K  [POT]  177.01,193.99 180 top
R108  6K8  [R-7]  196.37,176.85 180 top
R109  15K  [R-7]  196.37,186.37 180 top
R110  4K7  [R-10]  338.3,59.37 0 top
R111  10K  [R-10]  132.56,159.7 90 top
R112  390  [R-10]  141.45,154.62 0 top
R113  5K6  [R-10]  103.35,160.97 180 top
R114  10K  [POT]  215.11,160.97 0 top
R115  390  [R-10]  113.51,158.43 0 top
R116  NTC  [B57164]  110.97,164.78 180 top
R117  1K  [R-10]  122.4,136.21 180 top
R118  10K  [POT]  124.94,154.62 0 top
R119  1K  [R-10]  55.09,17.46 270 top
R120  51K  [R-10]  150.34,181.29 270 top
R121  100  [R-7]  36.04,13.65 180 top
R122  10K  [R-7]  13.18,20.96 270 top
R123  10K  [R-7]  21.43,13.65 180 top
R124  10  [R-7]  6.83,12.38 245 top
R125  100  [R-10]  28.42,52.07 90 top
R126  4K7  [R-10]  239.24,211.77 270 top
R127  4K7  [R-10]  221.77,211.77 90 top
R128  2K2  [R-7]  36.04,47.94 90 top
R129  2K2  [R-10]  38.58,46.67 90 top
R130  2K2  [R-10]  41.12,46.67 90 top
R131  3K3  [R-10]  36.04,35.24 90 top
R132  3K3  [R-10]  38.58,32.7 90 top
R133  3K3  [R-7]  41.12,30.8 90 top
R134  330  [R-7]  9.37,58.1 0 top
R135  330  [R-7]  20.8,58.1 0 top
R136  300  [R-10]  338.3,152.08 180 top
R137  0  [R-13]  325.6,142.56 270 top
R138  0  [R-15]  332.42,141.29 270 top
R139  0  [R-12]  321.79,145.1 270 top
R140  22K  [R-10]  347.19,53.02 270 top
R141  300  [R-10]  127.48,26.35 270 top
R142  300  [R-10]  142.72,26.35 270 top
R143  1K  [R-7]  127.48,39.21 270 top
R144  1K  [R-7]  142.72,39.21 270 top
R145  1K  [R-7]  121.13,37.78 0 top
R146  1K  [R-7]  136.37,37.78 0 top
R147  1K/1W  [R-10]  222.73,4.76 0 top
R148  1M  [R-10]  222.73,12.38 180 top
R149  2K2  [R-7]  190.98,9.84 270 top
R150  150  [R-10]  210.03,14.92 180 top
R151  1K  [R-7]  80.49,21.27 180 top
R152  100K  [R-10]  85.57,37.78 0 top
R153  10K  [R-10]  72.87,25.08 270 top
R154  ?  [R-10]  18.26,152.08 90 top
R155  ?  [R-10]  15.72,152.08 270 top
R156  220  [R-7]  62.71,37.78 0 top
R157  100\  [R-10]  81.76,30.16 0 top
R158  100K  [R-8]  90.65,32.7 180 top
R159  1K  [R-10]  85.57,35.24 180 top
RE1  [GDRX5]  352.27,33.97 90 top
RN1  [SIL9]  4.92,126.05 270 top
RN2  [SIL9]  352.9,87.31 90 top
RN3  [SIL9]  4.92,82.23 270 top
RN4  [SIL9]  352.9,133.67 90 top
RN5  [SIL9]  171.93,7.94 0 top
RS485  [AK500/2]  56.36,215.9 0 top
RST  TAC_SW_S  [SW]  124.94,88.58 270 top
S2  [DIP08YL]  11.91,124.78 90 top
S3  [DIP08YL]  345.92,88.58 270 top
S4  [DIP08YL]  11.91,80.96 90 top
S5  [DIP08YL]  345.92,134.94 270 top
S6  [DIP08YL]  173.2,14.92 180 top
S7  [B3F-10XX]  70.33,162.24 180 top
S8  [B3F-10XX]  70.33,154.62 180 top
S9  [B3F-40XX]  58.9,89.85 0 top
S10  [B3F-40XX]  76.68,89.85 0 top
S11  [B3F-40XX]  94.46,89.85 0 top
S12  [B3F-40XX]  112.24,89.85 0 top
S13  [B3F-10XX]  70.33,147 180 top
S14  [B3F-10XX]  70.33,139.38 180 top
S15  [B3F-40XX]  58.9,75.88 0 top
S16  [B3F-40XX]  76.68,75.88 0 top
S17  [B3F-40XX]  94.46,75.88 0 top
S18  [B3F-40XX]  112.24,75.88 0 top
S19  [B3F-10XX]  189.71,35.24 0 top
S20  [B3F-40XX]  58.9,61.91 0 top
S21  [B3F-40XX]  76.68,61.91 0 top
S22  [B3F-40XX]  94.46,61.91 0 top
S23  [B3F-40XX]  112.24,61.91 0 top
S24  [B3F-10XX]  189.71,42.86 0 top
S25  [B3F-40XX]  58.9,47.94 0 top
S26  [B3F-40XX]  76.68,47.94 0 top
S27  [B3F-40XX]  94.46,47.94 0 top
S28  [B3F-40XX]  112.24,47.94 0 top
S29  [B3F-10XX]  189.71,50.48 0 top
S30  [B3F-10XX]  189.71,58.1 0 top
S31  [DIP04YL]  94.46,183.83 180 top
S32  [DIP04YL]  215.11,183.83 180 top
S33  [DIP04YL]  156.69,75.88 270 top
S34  [DIP04YL]  300.2,200.34 180 top
S35  [DIP08YL]  207.49,70.8 0 top
S36  [DIP04YL]  57.63,193.99 180 top
S37  [DIP08YL]  37.31,160.34 180 top
S38  [B3F-10XX]  199.87,154.62 0 top
S39  [B3F-10XX]  199.87,163.51 0 top
S40  [B3F-10XX]  199.87,172.4 0 top
S41  [B3F-10XX]  199.87,181.29 0 top
S42  [DIP08YL]  160.5,160.97 0 top
S43  [DIP04YL]  37.31,59.37 0 top
S44  [MMC-SD-CARD-P]  6.83,42.86 0 top
SPK  [AK500/2]  61.44,4.76 180 top
SW1  [SWITCH]  4.29,211.77 270 top
SW2  [ON_OFF]  216.38,106.36 270 top
SW3  [ON_OFF]  324.96,121.6 0 top
TR1  8050  [TO92L]  58.9,12.38 90 top
TR2  [GDTX6]  334.49,8.57 0 top
U1  [HEADER64PIN]  163.04,116.52 0 top
U$1  SMARTCARD  [CARDSOCKET]  337.03,187.64 0 top
Z1  4V7  [DO35-7B]  137.64,83.5 90 top
Z2  4V7  [DO35-7B]  140.18,80.96 90 top
Z3  3V3  [SOD120]  32.23,40.64 270 top
Z4  12V  [SOD81]  210.03,20 0 top
Z5  5V1  [SOD81]  210.03,12.38 0 top
Z6  12V  [SOD81]  210.03,17.46 0 top

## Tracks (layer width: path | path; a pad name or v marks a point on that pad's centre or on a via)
+3V3
  Top 1.016: S44.4 28.22,42.74 C59.2
  Bottom 1.016: 30.96,46.99 Z3.C | 30.96,46.99 R125.1 C59.2 | C60.1 30.96,46.99
+VIR
  Bottom 1.016: IC14.VCC C57.1 R121.2
AR1
  Bottom 1.016: S36.8 arc90 57.63,193.99 55.69,193.99 arc-90 50.01,199.67 R72.1
AR2
  Bottom 1.016: S36.1 61.44,199.82 arc-45 61.81,200.71 62.33,201.24 arc45 62.71,202.14 R71.1
AR11
  Bottom 1.016: R72.2 53.82,213.04
  Bottom 1.27: IC9.7 55.09,211.25 arc45 54.71,212.14 53.82,213.04 53.82,214.31 RS485.1
ASAS
  Bottom 1.016: R122.1 arc90 C58.1 JP17.2
BC-CLK
  Bottom 1.016: R137.1 325.6,179.88 arc90 319.74,185.74 U$1.CLK
BC-IO
  Bottom 1.016: R138.1 334.34,148.91 arc90 338.3,153.66 338.3,167.96 arc-90 U$1.I/O
BC-OK
  Bottom 1.016: LED20.A 329.41,185.22 arc90 322.54,192.09 U$1.SW2
BC-RST
  Bottom 1.016: R139.1 321.79,180.91 arc90 319.5,183.2 U$1.RST
CTR
  Bottom 1.016: LCD.3 235.42,111.45 arc90 R29.S
GETRC
  Bottom 1.016: R114.A arc45 215.11,162.02 R114.S arc-45 213.84,169.12 JP14.1
GLCD-V0
  Bottom 1.016: GLCD.3 280.4,119.68 arc90 287.36,112.71 R30.S
GLCD-VOUT
  Bottom 1.016: GLCD.18 242.3,122.19 242.25,122.24 242.25,120.33 arc90 244.79,117.79 271.09,117.79 arc-45 276.06,115.73 278.69,113.1 arc45 285.77,110.17 R30.A
GND  (via drill 0.6 pad 1.52, 0.6 pad 1.68)
  Top 0.813: C59.1 27.94,39.53 S44.3 21.66,39.53
  Top 1.016: 21.66,39.53 arc-45 17.21,41.37 11.63,46.95 arc-45 9.37,52.41 9.37,58.1 arc-90 11.91,60.64 arc-90 15.72,58.1 15.72,53.6 arc45 17.21,50 17.7,49.5 arc45 21.85,47.78 S44.6 | GLCD.20 237.33,122.24 | 212.57,147 J3.2
  Top 1.27: C10.1 117.32,201.07 arc-90 119.13,202.88 IC2.10 | R120.1 147.72,183.76 arc45 143.99,174.74 PS1.3 C53.1 | v333.22,115.25 v322.42,115.25 | IC12.1 347.91,66.99 arc-90 355.92,58.98 355.92,48.17 arc-90 353.15,45.4 RE1.3 | R29.E 235.05,121.22 arc-45 GLCD.20 | C68.2 arc-45 197.38,22.6 200.55,25.76 arc45 202.41,30.25 202.41,38.28 arc-90 206.99,42.86 226.54,42.86 | 226.54,42.86 235.13,42.86 arc-90 237.97,40.02 IC8.8 | IC8.13 228.02,27.62 arc-45 225.48,28.67 224.9,29.26 arc45 219.66,31.43 JP9.2 | v158.27,25.72 v187.17,25.72 | LCD.1 228.03,102.56 arc45 225.49,101.51 224.62,100.64 arc45 222.73,96.06 222.73,54.38 arc45 224.59,49.89 arc-45 226.54,45.18 226.54,42.86 | C45.1 212.57,147 212.57,126.46 arc45 v215.11,120.33 | v99.54,192.72 v91.92,192.72 | J4.1 J4.2 | J5.1 J5.2 | J6.1 J6.2 | J2.2 J2.1
  Bottom 0.61: LPT.19 137.64,210.5 | LPT.22 145.89,210.5 | LPT.23 148.75,210.5 | LPT.25 154.15,210.5 | 134.78,210.5 LPT.18 | 157.96,219.39 134.78,219.39 119.86,219.39 IC2.10 | C12.1 110.97,214.31 | C11.2 C10.1 | 68.1,205.58 C15.2 | 68.1,205.58 68.1,209.23 COM1.G1 68.1,209.37 68.1,210.5 68.1,213.04 70.64,215.58 93.03,215.58 93.01,215.56 COM1.G2 93.03,209.23 91.76,207.96 COM1.5 | IC3.15 75.41,204.79 74.61,205.58 68.1,205.58 | 187.17,209.23 COM2.G1 | 187.17,205.58 C20.2 | 187.17,209.23 187.17,205.58 | IC4.15 194.79,204.79 193.99,205.58 187.17,205.58 | 212.57,209.23 COM2.G2 | COM2.5 212.57,207.96 212.57,209.23 | 187.17,209.23 187.17,213.04 187.17,215.58 212.57,215.58 212.57,209.23
  Bottom 0.813: C14.1 105.89,171.13 108.43,171.13 | 108.43,171.13 113.51,171.13 117.32,171.13 C11.2 | 108.43,171.13 C13.1 | C19.1 90.65,191.45 v91.92,192.72 | 103.35,192.72 v99.54,192.72
  Bottom 1.016: LPT.25 LPT.24 LPT.23 LPT.22 LPT.21 LPT.20 LPT.19 134.78,210.5 134.78,219.39 | GLCD.1 285.48,121.6 arc90 288.02,119.06 309.92,119.06 arc-45 315,116.96 R30.E v322.42,115.25 | LCD.1 227.8,102.56 224,106.36 R29.E | IC8.8 235.43,37.78 | 235.43,37.78 235.43,27.62 IC8.13 | 311.63,28.89 311.63,18.73 IC7.8 | 311.63,28.89 IC7.13 352.27,28.89 | 311.63,28.89 C29.1 | 143.99,149.54 R118.E 127.48,152.08 126.21,153.35 124.94,153.35 | 143.99,149.54 146.53,149.54 U1.63 | U1.63 146.53,141.92 | U1.63 C2.2 C3.2 171.93,141.92 | 171.93,141.92 U1.53 | U1.22 C1.2 156.69,102.55 150.34,102.55 C4.2 | U1.24 U1.23 U1.22 | U1.22 C28.2 156.69,84.77 Z2.A 137.64,84.77 | 100.81,149.54 C47.1 C50.1 105.89,150.81 C49.2 113.51,153.35 | 100.81,149.54 C48.1 | IC9.5 60.17,206.69 C32.1 44.93,206.69 | 44.93,206.69 C31.2 | IC10.4 C35.1 4.29,171.13 LDAC.1 | IC10.4 R97.1 R98.1 4.29,166.05 4.29,154.62 | IC10.4 12.65,171.13 arc90 14.45,172.93 C34.1 C33.2 5.56,183.83 5.56,188.91 28.42,188.91 C6.1 44.93,195.26 | JP6.1 JP7.2 55.09,171.13 50.01,171.13 50.01,186.69 R88.1 | 205.9,179.03 S41.4 203.04,179.03 | 205.9,161.29 205.9,152.4 203.68,152.4 | 205.9,161.29 205.9,170.18 | 205.9,170.18 205.9,179.03 | 203.68,152.4 203.04,152.4 203.04,152.36 | 203.04,152.36 S38.4 | 203.04,152.36 S38.3 192.56,152.36 | 203.04,161.25 S39.4 205.9,161.25 205.9,161.29 | 203.04,161.25 S39.3 | 203.04,161.25 203.04,161.29 | 203.04,170.14 S40.4 205.9,170.14 205.9,170.18 | 203.04,170.14 S40.3 | 203.04,170.14 203.04,170.18 | 203.04,179.03 S41.3 | 203.04,179.03 203.04,179.07 | 205.9,179.03 205.9,184.79 208.76,187.64 C24.1 | 192.56,152.36 C40.1 | 150.34,182.56 141.45,182.56 C52.2 | 150.34,182.56 C54.1 156.69,182.56 C37.1 C39.1
  Bottom 1.016: 150.34,182.56 R120.1 R100.E 161.77,200.34 157.96,204.15 157.96,219.39 | 124.94,153.35 R118.S 124.94,162.24 arc-90 C42.1 | PH1.2 C43.1 143.99,149.54 | 113.51,160.97 113.51,153.35 | 113.51,160.97 R116.1 113.51,171.13 | 113.51,153.35 124.94,153.35 | 113.51,160.97 C46.1 | 100.81,149.54 C44.1 | 189.07,152.36 186.57,152.36 D4.C R105.2 172.24,152.4 171.93,152.08 | 189.07,152.36 192.56,152.36 | C38.2 171.93,157.48 171.93,152.08 | 171.93,141.92 171.93,152.08 | 189.07,152.36 189.07,162.24 C36.2 | 180.82,219.39 183.36,219.39 187.17,215.58 | C20.2 174.47,202.88 R107.E | R88.1 46.2,186.37 | 44.93,195.26 46.2,195.26 R88.1 | PS2.3 233.75,202.98 234.16,202.96 | 234.16,202.96 C61.2 | R132.1 30.96,27.62 | R132.1 R133.1 43.66,27.62 | 30.96,34.29 C59.1 | 30.96,27.62 30.96,34.29 | 30.96,34.29 Z3.A | R131.1 38.58,30.16 R132.1 | C60.2 33.5,49.21 34.77,47.94 43.66,47.94 43.66,27.62 | 124.94,59.37 IC5.1 IC5.2 IC5.3 IC5.4 136.37,61.91 C27.2 C26.1 | 124.94,59.37 C25.2 | C26.1 155.42,61.91 IC6.4 | C26.1 J1.2 J1.1 136.84,53.02 | 124.94,84.77 137.64,84.77 | 124.94,84.77 RST.2 | 137.64,84.77 Z1.A | IC14.GND C57.2 32.23,22.54 | C56.2 C55.1 LED17.K 46.2,1.91 1.75,1.91 1.75,95.57 | 32.23,22.54 30.96,23.81 30.96,27.62 | 345.92,152.08 R136.1 | 345.92,152.08 C.2 351,180.66 U$1.GND | 345.92,152.08 345.92,125.57 343.38,123.03 JP4.3 343.38,115.25 | C63.2 335.76,13.65 TR2.2 | C71.2 C70.2 11.91,154.6 PDAC.2 4.29,154.62 | 343.38,66.99 C41.2 | 343.38,66.99 JP2.3 343.38,77.15 345.92,79.69 345.92,100.02 | 343.38,66.99 IC12.1 | 119.22,37.78 R145.1 | 119.22,37.78 Q15.3 108.59,34.13 103.35,28.89 JP27.1 | 134.46,37.78 R146.1 133.03,37.78 | Q16.3 134.46,37.78 | C56.2 58.9,17.78 58.9,17.46
  Bottom 1.016: 58.9,17.46 TR1.1 | C56.2 46.2,25.08 43.66,27.62 | PWR3.2 151.61,4.76 151.61,17.46 JP5.3 v158.27,25.72 B2.- 152.56,31.75 145.26,40.32 137.64,40.32 | 235.43,37.78 C30.1 | C68.2 arc90 193.83,17.62 OK1.5 C67.1 190.34,18.09 arc-45 187.17,25.77 | 187.17,25.77 JP8.1 | C62.2 336.06,23.81 arc90 333.22,20.97 | 345.92,106.39 PWR4.2 | 345.92,106.39 arc-90 343.38,108.93 343.38,115.25 | 343.38,115.25 v333.22,115.25 | 345.92,100.02 268.45,100.01 arc-90 268.44,100.02 LCD.16 268.45,106.36 245.59,106.36 | 345.92,100.02 345.92,106.39 | LCD.5 | LCD.5 | 240.51,106.36 245.59,106.36 | 240.51,106.36 LCD.5 | LCD.9 LCD.8 | LCD.9 LCD.10 | LCD.9 | LCD.8 LCD.7 | LCD.8 | LCD.7 | LCD.7 | 245.59,106.36 LCD.7 | GLCD.20 237.22,122.19 237.17,122.24 237.17,119.06 | 240.51,106.36 240.51,108.57 arc45 238.7,112.93 arc-45 237.17,116.62 237.17,119.06 | 212.57,215.58 212.57,207.96 218.92,207.96 218.92,202.88 234.16,202.88 234.16,202.96 | 187.17,213.04 PWR2.2 | 1.75,95.57 1.75,107.63 1.77,107.61 PWR1.2 1.75,107.61 1.75,139.38 | 1.75,139.38 1.75,154.62 4.29,154.62 | 1.75,139.38 JP1.3 | 119.22,37.78 119.22,39.69 122.4,42.86 122.4,53.02 136.84,53.02 | 137.64,40.32 137,40.32 134.46,37.78 | OK2.2 58.9,35.24 58.9,17.46 | JP17.3 21.43,19.37 22.7,21.91 32.23,22.54 | 124.94,84.77 122.4,84.77 122.4,59.37 124.94,59.37 | 44.93,195.26 44.93,206.69 | 1.75,95.57 JP3.3 | v187.17,25.72 187.17,25.77 | v215.11,120.33 216.38,119.06 237.17,119.06 | 203.68,152.4 J3.1 | 93.03,209.23 99.7,209.23 99.7,196.37 103.35,192.72 103.35,182.56 C14.1 | 136.84,53.02 137.64,53.02 137.64,40.32
  Bottom 1.27: B1.- C5.2 18.26,200.34 22.07,204.15 R2.1 28.42,206.69 | C6.1 IC1.GND 28.42,206.69 | 28.42,206.69 C7.2 C8.2 C9.1 | IC9.5 68.1,210.5
  Bottom 1.778: C62.2 RE1.2 352.27,28.89 RE1.3 C64.2
  pour Bottom (isolate 0.813, no thermals): 370.05,227.01 370.05,-4.13 231.62,-5.4 231.62,23.81 198.6,23.81 199.23,-6.67 142.72,-6.03 142.72,26.35 112.24,26.35 111.6,-6.03 -5.87,-6.03 -5.87,-4.13 -5.87,227.01
  pour Top (isolate 0.762, no thermals, hatched): 130.65,149.54 195.42,149.54 195.42,84.77 130.65,84.77
  pour Top (isolate 0.762, no thermals, hatched): 223.04,189.55 316.07,189.55 316.07,119.7 223.04,119.7
  pour Top (isolate 0.762, no thermals, hatched): 220.19,105.09 318.29,105.09 318.29,45.08 220.19,45.08
  pour Top (isolate 0.762, no thermals, hatched): 240.82,43.18 306.23,43.18 306.23,10.8 240.82,10.8
  pour Top (isolate 0.762, no thermals, hatched): 308.77,37.78 317.02,37.78 317.02,17.46 308.77,17.46
  pour Top (isolate 0.762, no thermals, hatched): 316.71,218.76 359.25,218.76 359.25,156.84 315.75,156.84 316.07,189.23 316.39,189.55 316.39,218.44
  pour Top (isolate 0.762, no thermals, hatched): 184.31,206.06 184.31,220.66 215.42,220.66 215.42,206.06
  pour Top (isolate 0.762, no thermals, hatched): 112.24,220.98 112.24,206.06 165.26,206.06 165.26,220.66 112.55,220.66
  pour Top (isolate 0.762, no thermals, hatched): 64.93,220.66 64.93,206.06 95.73,206.06 95.73,220.66
  pour Top (isolate 0.762, no thermals, hatched): 0.16,26.99 0.16,56.2 23.65,56.2 23.65,26.99
  pour Top (isolate 0.762, no thermals, hatched): 355.12,55.56 355.12,16.19 347.19,16.19 347.19,55.56
  pour Top (isolate 0.762, no thermals, hatched): 340.84,10.48 340.84,6.67 328.14,6.67 328.14,10.48
  pour Top (isolate 0.762, no thermals, hatched): 10.95,165.42 10.64,182.25 9.68,183.2 9.68,184.47 15.8,184.47 arc-90 19.84,180.43 19.84,165.42
  pour Top (isolate 0.762, no thermals, hatched): 123.98,68.26 156.69,68.26 156.69,51.44 123.67,51.44 123.67,68.26
  pour Top (isolate 0.762, no thermals, hatched): 62.71,202.88 49.96,202.88 46.83,206.01 46.83,210.5 62.71,210.5
  pour Top (isolate 0.762, no thermals, hatched): 137.64,186.37 147.48,186.37 147.48,173.99 137.64,173.99
GROUP-A1
  Bottom 1.016: JP21.2 arc90 125.41,42.39 R143.1
GROUP-A2
  Bottom 1.016: R144.1 140.65,42.39 arc-90 JP22.2
INT0
  Bottom 1.016: 150.34,72.07 S33.4 | 150.34,72.07 IC6.7 | R32.1 150.34,72.07
IR
  Bottom 1.016: IC14.OUT R123.1 JP18.1
J
  Bottom 0.406: 83.23,213.04 COM1.4
  Bottom 0.61: 81.76,213.04 81.99,213.04
  Bottom 1.016: COM1.1 75.09,207.96 arc-45 75.98,210.11 COM1.6 78.16,212.29 arc-45 79.97,213.04 81.76,213.04 83.23,213.04
K
  Bottom 0.406: 202.61,213.04 COM2.4
  Bottom 0.61: 195.74,210.5 COM2.6
  Bottom 1.016: COM2.1 194.38,208.09 arc-45 195.12,209.89 195.74,210.5 | COM2.6 arc-90 198.29,213.04 201.14,213.04 202.61,213.04
LDR
  Bottom 1.016: R112.2 C43.2 148.01,160.97 arc90 151.61,164.56 S42.16
LM35-1
  Bottom 1.016: 173.2,161.92 R102.2 | 173.2,161.92 169.23,161.92 arc-90 S42.10 | 173.2,161.92 173.51,161.92 arc-37 C38.1
LM35-2
  Bottom 1.016: D3.A IC11.3 171.93,167.32 arc90 S42.9
ML1
  Top 0.813: 296.39,36.51 M1.9
  Top 1.016: M2.9 271.86,33.1 arc45 275.88,31.43 285.88,31.43 arc45 289.72,33.02 292.44,35.75 arc-45 294.3,36.51 296.39,36.51
  Bottom 1.016: M2.9 265.91,39.7 arc45 264.57,42.93 Q6.3
ML2
  Top 1.016: M2.14 253.21,39.15 arc-45 254.04,41.15 255.35,42.47 arc-45 259.37,44.13 278.91,44.13 arc45 282.72,45.71 Q7.3 arc-90 286.23,44.13 M1.14
ML3
  Top 1.016: Q8.3 arc-90 301.47,44.13 301.47,26.26 arc-45 300.63,24.25 299.76,23.37 arc45 298.93,21.37 M1.8 298.93,12.03 arc-90 294.52,7.62 270.32,7.62 arc-90 265.91,12.03 M2.8
ML4
  Top 1.016: M2.12 258.29,40.32 arc-90 259.56,41.59 264.55,41.59 arc-45 269.04,39.73 273.46,35.31 arc45 276.69,33.97 285.83,33.97 arc45 288.67,35.15 290.41,36.88 arc45 M1.12 Q9.3
ML5
  Bottom 0.813: M1.1 arc-90 278.92,12.7 250.35,12.7 arc-90 M2.1
  Bottom 1.016: M1.1 281.15,27.64 arc45 278.46,34.11 278.42,34.16 arc-45 276.07,39.84 Q10.3
ML6
  Top 1.016: M2.7 arc-90 265.59,17.14 265.91,17.14 arc-90 268.45,14.6 arc90 273.53,10.16 292.26,10.16 arc90 M1.7
  Bottom 1.016: Q11.3 268.45,26.07 arc-45 265.95,20.05 265.03,19.13 arc45 263.37,15.11 M2.7
ML7
  Top 1.016: Q12.3 arc90 243.05,44.13 243.05,22.04 arc90 247.63,17.46 248.87,17.46 arc-90 250.67,15.67 M2.2
  Bottom 0.813: M1.2 283.69,13.33 arc-90 281.15,10.8 249.4,10.8 arc-90 245.59,14.6 245.59,15.67 arc-90 247.38,17.46 248.87,17.46 arc-90 250.67,15.67 M2.2
ML8
  Top 1.016: M2.5 258.29,19.05 | 258.29,19.05 268.45,19.05 arc-90 270.99,16.51 270.99,15.24 arc90 273.53,12.7 289.08,12.7 arc90 M1.5 | 258.29,19.05 arc-90 253.21,24.13 253.21,24.86 arc45 249.01,34.99 246.52,37.49 arc-45 245.59,39.73 245.59,40.54 arc-90 249.18,44.13 250.67,44.13 arc90 Q13.3
MULTI_SW
  Bottom 1.016: 192.56,176.21 R104.2 R103.2 C40.2 | 192.56,176.21 R108.2 R109.2 R101.S | 192.56,176.21 R101.E 187.17,176.26 arc90 183.56,179.87 arc45 179.51,177.45 176.23,171.52 arc-61 173.41,169.86 169.39,169.86 arc90 S42.11
N$1
  Bottom 1.016: R49.2 IC7.7
N$2
  Bottom 1.27: 14.45,213.04 PWR.-
  Bottom 1.676: B1.AC2 6.39,196.97 arc-45 5.56,198.98 5.56,201.31 arc-90 8.4,204.15 15.93,204.15 arc90 19.53,207.74 19.53,207.96 arc90 14.45,213.04
N$3
  Bottom 1.676: IC1.IN D1.C C6.2 C5.1 14.35,192.63 arc-45 11.51,191.45 5.86,191.45 arc-90 3.02,194.29 B1.+
N$4
  Bottom 1.27: R2.2 21.57,214.58 arc-29 21.11,216.39 LED1.K
N$5
  Bottom 1.016: R3.2 104.62,202.88 arc-90 101.44,206.06 101.44,208.01 arc-45 102.76,211.18 LED2.K
N$6
  Bottom 1.016: JP1.2 arc-90 8.73,136.21 RN1.1
N$7
  Bottom 1.016: JP3.2 11.91,94.19 arc-90 10.11,92.39 RN3.1
N$8
  Bottom 1.016: S4.9 RN3.2
N$9
  Bottom 1.016: S14.4 67.35,141.92 73.3,141.92 S14.3 73.58,141.92 73.84,141.92 arc90 76.68,144.76 76.68,149.54 | 70.33,164.78 JP6.2 | S13.4 67.35,149.54 73.3,149.54 S13.3 73.58,149.54 76.68,149.54 | S8.4 67.35,157.16 73.3,157.16 S8.3 73.58,157.16 76.68,157.16 | S7.4 67.35,164.78 70.33,164.78 | 70.33,164.78 73.3,164.78 S7.3 73.86,164.78 arc-90 76.68,161.96 76.68,157.16 | 76.68,149.54 76.68,157.16
N$10
  Bottom 1.016: C18.1 74.04,191.55 arc-45 72.87,194.39 IC3.1
N$11
  Bottom 0.813: 186.53,55.84 S30.3 | S30.4 186.53,55.84 | 186.53,55.84 186.53,55.88 | S29.4 192.92,48.22 192.88,48.26 192.84,48.22 S29.3 | 193.16,40.6 S24.4 | 193.16,40.6 S24.3 | 193.2,40.64 193.16,40.6 | S19.4 192.92,32.98 192.88,33.02 192.84,32.98 189.71,32.98 S19.3
  Bottom 1.016: 184.31,40.64 184.31,48.26 | 184.31,48.26 184.31,53.96 arc-90 186.19,55.84 S30.4 | S19.3 186.53,32.98 186.53,33.02 arc-90 184.31,35.24 184.31,40.64 | 184.31,40.64 193.2,40.64 | S29.4 184.31,48.22 184.31,48.26 | JP8.2 189.71,32.98
N$12
  Bottom 1.016: S2.9 RN1.2
N$13
  Bottom 1.016: S2.10 RN1.3
N$14
  Bottom 1.016: S2.11 RN1.4
N$15
  Bottom 1.016: S2.12 RN1.5
N$16
  Bottom 1.016: S2.13 RN1.6
N$17
  Bottom 1.016: S2.14 RN1.7
N$18
  Bottom 1.016: S2.15 RN1.8
N$19
  Bottom 1.016: S2.16 RN1.9
N$20
  Bottom 1.016: S4.10 RN3.3
N$21
  Bottom 1.016: S4.11 RN3.4
N$22
  Bottom 1.016: S4.12 RN3.5
N$23
  Bottom 1.016: S4.13 RN3.6
N$24
  Bottom 1.016: S4.14 RN3.7
N$25
  Bottom 1.016: S4.15 RN3.8
N$26
  Bottom 1.016: S4.16 RN3.9
N$27
  Bottom 0.813: RN5.1 161.77,12.19 arc90 159.04,14.92 JP5.2
N$28
  Bottom 1.016: RN5.2 S6.9
N$29
  Bottom 1.016: RN5.3 S6.10
N$30
  Bottom 1.016: RN5.4 S6.11
N$31
  Bottom 1.016: RN5.5 S6.12
N$32
  Bottom 1.016: RN5.6 S6.13
N$33
  Bottom 1.016: RN5.7 S6.14
N$34
  Bottom 1.016: RN5.8 S6.15
N$35
  Bottom 1.016: RN5.9 S6.16
N$36
  Bottom 1.016: S10.1 70.33,92.34 | 70.33,92.34 S9.2 | 70.33,92.34 70.33,92.39
N$37
  Bottom 1.016: 88.11,92.34 S11.1 | S10.2 88.11,92.34 | 88.11,92.34 88.11,92.39
N$38
  Bottom 1.016: 105.89,92.34 S12.1 | S11.2 105.89,92.34 | 105.89,92.34 105.89,92.39
N$39
  Bottom 1.016: 65.25,64.4 S20.2 | S21.1 65.25,64.4 | 65.25,64.4 65.25,64.45
N$40
  Bottom 1.016: 83.03,64.4 S21.2 | S22.1 83.03,64.4 | 83.03,64.4 83.03,64.45
N$41
  Bottom 1.016: 105.89,64.4 S23.1 | 105.89,64.4 S22.2 | 105.89,64.4 105.89,64.45
N$42
  Bottom 1.016: JP4.2 345.92,122.09 arc-90 347.34,123.51 RN4.1
N$43
  Bottom 1.016: S5.9 RN4.2
N$44
  Bottom 1.016: S5.10 RN4.3
N$45
  Bottom 1.016: S5.11 RN4.4
N$46
  Bottom 1.016: S5.12 RN4.5
N$47
  Bottom 1.016: S5.13 RN4.6
N$48
  Bottom 1.016: S5.14 RN4.7
N$49
  Bottom 1.016: S5.15 RN4.8
N$50
  Bottom 1.016: S5.16 RN4.9
N$51
  Bottom 1.016: RN2.1 347.71,77.15 arc90 345.92,75.36 JP2.2
N$52
  Bottom 1.016: S3.9 RN2.2
N$53
  Bottom 1.016: S3.10 RN2.3
N$54
  Bottom 1.016: S3.11 RN2.4
N$55
  Bottom 1.016: S3.12 RN2.5
N$56
  Bottom 1.016: S3.13 RN2.6
N$57
  Bottom 1.016: S3.14 RN2.7
N$58
  Bottom 1.016: S3.15 RN2.8
N$59
  Bottom 1.016: S3.16 RN2.9
N$60
  Bottom 1.016: 65.25,78.37 S15.2 | S16.1 65.25,78.37 | 65.25,78.37 65.25,78.42
N$61
  Bottom 1.016: 83.03,78.37 S16.2 | S17.1 83.03,78.37 | 83.03,78.37 83.03,78.42
N$62
  Bottom 1.016: 105.89,78.37 S18.1 | S17.2 105.89,78.37 | 105.89,78.37 105.89,78.42
N$63
  Bottom 1.016: C18.2 76.89,191.67 arc45 77.95,194.21 IC3.3
N$64
  Bottom 1.016: C17.1 IC3.4
N$65
  Bottom 1.016: 65.25,50.43 S25.2 | S26.1 65.25,50.43 | 65.25,50.43 65.25,50.48
N$66
  Bottom 1.016: 83.03,50.43 S26.2 | S27.1 83.03,50.43 | 83.03,50.43 83.03,50.48
N$67
  Bottom 1.016: S9.4 64.6,87.36 arc90 58.9,81.66 58.9,77.93 arc-90 54.36,73.39 S15.3
N$68
  Bottom 1.016: S10.4 82.06,87.36 arc45 79.37,86.25 77.79,84.67 arc45 76.68,81.98 76.68,78.73 arc-45 75.56,76.04 74.03,74.51 arc-45 71.34,73.39 S16.3
N$69
  Bottom 1.016: S17.3 89.07,73.39 arc45 91.76,74.51 93.34,76.09 arc45 94.46,78.78 94.46,81.98 arc-45 95.57,84.67 97.15,86.25 arc-45 99.84,87.36 S11.4
N$70
  Bottom 1.016: S12.4 117.62,87.36 arc45 114.93,86.25 113.35,84.67 arc45 112.24,81.98 112.24,78.73 arc-45 111.12,76.04 109.54,74.46 arc-45 106.85,73.34 105.94,73.34 | 105.89,73.34 105.94,73.34 | 105.94,73.34 S18.3
N$71
  Bottom 1.016: S28.1 105.89,50.43 | 105.89,50.43 S27.2 | 105.89,50.43 105.89,50.48
N$72
  Bottom 1.016: C17.2 IC3.5
N$73
  Bottom 1.016: S25.3 52.55,45.45 52.55,45.4 53.51,45.4 arc45 56.2,46.52 57.78,48.1 arc45 58.9,50.79 58.9,54.04 arc-45 60.01,56.73 61.59,58.31 arc-45 64.28,59.42 S20.4
N$74
  Bottom 1.016: S26.3 70.33,45.45 70.33,45.4 71.29,45.4 arc45 73.98,46.52 75.56,48.1 arc45 76.68,50.79 76.68,54.04 arc-45 77.79,56.73 79.37,58.31 arc-45 82.06,59.42 S21.4
N$75
  Bottom 1.016: S22.4 99.84,59.42 arc45 97.15,58.31 95.57,56.73 arc45 94.46,54.04 94.46,50.79 arc-45 93.34,48.1 91.76,46.52 arc-45 89.07,45.4 88.11,45.4 88.11,45.45 S27.3
N$76
  Bottom 1.016: S23.4 118.43,59.37 117.62,59.37 arc45 114.93,58.26 113.35,56.68 arc45 112.24,53.98 112.24,50.79 arc-45 111.12,48.1 109.54,46.52 arc-45 106.85,45.4 105.94,45.4 | 105.94,45.4 105.89,45.4 | 105.94,45.4 S28.3
N$77
  Bottom 1.016: S15.4 65.2,73.39 65.25,73.34 64.07,73.34 arc45 61.37,72.23 60.01,70.87 arc45 58.9,68.17 58.9,64.76 arc-45 57.78,62.07 56.25,60.54 arc-45 53.56,59.42 S20.3
N$78
  Bottom 1.016: S16.4 81.88,73.39 arc45 79.19,72.28 77.79,70.88 arc45 76.68,68.19 76.68,64.76 arc-45 75.56,62.07 73.98,60.49 arc-45 71.29,59.37 70.33,59.37 70.38,59.42 S21.3
N$79
  Bottom 1.016: S17.4 99.66,73.39 arc45 96.97,72.28 95.57,70.88 arc45 94.46,68.19 94.46,64.76 arc-45 93.34,62.07 91.76,60.49 arc-45 89.07,59.37 88.11,59.37 88.16,59.42 S22.3
N$80
  Bottom 1.016: S18.4 117.44,73.39 arc45 114.75,72.28 113.35,70.88 arc45 112.24,68.19 112.24,64.76 arc-45 111.12,62.07 109.54,60.49 arc-45 106.85,59.37 105.89,59.37 105.94,59.42 S23.3
N$81
  Bottom 1.016: C19.2 86.74,191.55 arc-45 85.57,194.39 IC3.6
N$82
  Bottom 1.016: IC3.2 75.41,196.01 arc90 73.61,197.8 72.34,197.8 arc45 71.07,197.28 69.73,195.94 arc-45 C16.1
N$83
  Bottom 0.61: IC3.9 92.1,202.88 arc-90 96.36,198.62 96.36,191.51 arc45 96.97,190.05 97.89,189.13 arc-45 98.27,188.22 S31.1
N$84
  Bottom 0.61: IC3.12 arc-45 83.58,204.23 84.24,204.89 arc-45 85.92,205.58 92.55,205.58 arc-90 97.63,200.5 97.63,192.78 arc45 98.24,191.32 99.23,190.33 arc-45 100.17,188.06 100.17,187.1 arc-90 98.17,185.1 arc-45 96.16,185.93 96.1,186 arc-45 95.73,186.9 S31.2
N$85
  Bottom 0.61: IC3.10 88.11,202.14 arc90 89.9,200.34 92.8,200.34 arc-90 95.09,198.05 95.09,191.82 arc-45 94.27,189.84 93.97,189.54 arc45 S31.3
N$86
  Bottom 0.61: IC3.11 85.57,201.91 arc90 88.41,199.07 92.4,199.07 arc-90 93.82,197.65 93.82,193.43 arc-45 92.87,191.14 91.48,189.74 arc45 90.65,187.74 S31.4
N$87
  Bottom 1.016: C23.1 arc-45 192.25,194.52 IC4.1
N$88
  Bottom 1.016: C23.2 arc45 197.33,194.52 IC4.3
N$89
  Bottom 1.016: C22.1 IC4.4
N$90
  Bottom 1.016: C22.2 IC4.5
N$91
  Bottom 1.016: C24.2 206.12,191.55 arc-45 204.95,194.39 IC4.6
N$92
  Bottom 1.016: C21.1 arc45 189.33,196.16 190.45,197.28 arc-45 191.72,197.8 192.99,197.8 arc-90 194.79,196.01 IC4.2
N$93
  Bottom 0.61: IC4.9 212.57,202.88 arc-90 215.11,200.34 215.11,195.04 arc45 215.85,193.25 218.17,190.93 arc-45 218.92,189.13 S32.1
N$94
  Bottom 0.61: S32.2 216.38,187.12 arc45 216.9,185.85 arc45 218.7,185.1 219.66,185.1 arc90 221.46,186.9 221.46,188.01 arc45 219.92,191.72 217.12,194.52 arc-45 216.38,196.31 216.38,201.83 arc90 212.78,205.42 204.73,205.42 arc45 202.93,204.68 arc45 202.41,203.41 IC4.12
N$95
  Bottom 0.61: IC4.10 arc90 210.03,200.34 211.3,200.34 arc-90 213.84,197.8 S32.3
N$96
  Bottom 0.61: S32.4 211.3,191.98 arc-45 211.82,193.25 arc45 212.57,195.04 212.57,196.53 arc90 210.03,199.07 207.49,199.07 arc-90 204.95,201.61 IC4.11
N$97
  Bottom 1.016: LED11.K R25.2
N$98
  Top 0.813: 19.88,42.51 arc45 23.24,41.12 S44.S2
  Top 1.016: R134.2 13.18,51.89 arc45 15.07,47.32 19.88,42.51
N$99
  Bottom 1.016: LED18.K R134.1
N$100
  Top 1.016: S44.S1 24.72,57.99 R135.2
N$101
  Bottom 1.016: LED19.K R135.1
N$102
  Top 1.016: S44.5 26.04,45.24 27.78,44.77 R128.1
  Bottom 1.016: R128.1 R131.2
N$103
  Top 1.016: S44.2 38.54,37.74 R132.2
  Bottom 1.016: R129.1 R132.2
N$104
  Top 1.016: R133.2 37.73,34.61 arc45 35.38,33.64 34.15,32.4 arc-45 32.58,31.75 31.95,31.75 arc-43 30.22,32.42 27.96,34.5 arc43 26.04,35.24 24.61,35.24 S44.1
  Bottom 1.016: R130.1 R133.2
N$105  (via drill 0.6 pad 1.68)
  Top 0.813: 26.99,50.32 S44.7
  Top 1.016: 30.69,54.03 v30.64,53.97 26.99,50.32
  Bottom 1.016: S43.1 arc45 31.33,54.66 v30.64,53.97
N$106
  Bottom 1.016: DSP1.11 264.64,210.06 arc-45 262.25,204.31 259.4,201.45 arc45 257.02,195.7 R39.2
N$107
  Bottom 1.016: S43.4 R130.2
N$108
  Bottom 1.016: S43.3 R129.2
N$109
  Bottom 1.016: S43.2 R128.2
N$110
  Bottom 1.016: R40.2 277.34,209.87 arc90 DSP1.7
N$111
  Bottom 1.016: R41.2 DSP1.4
N$112
  Bottom 1.016: R42.2 DSP1.2
N$113
  Bottom 1.016: R43.2 DSP1.1
N$114
  Bottom 1.016: R44.2 259.56,195.17 arc-45 261.42,199.66 264.79,203.04 arc45 267.18,208.79 DSP1.10
N$115
  Bottom 1.016: R45.2 DSP1.5
N$116
  Bottom 1.016: R46.2 DSP1.3
N$117
  Bottom 1.016: R36.1 304.01,214.31 arc-90 301.47,211.77 296.69,211.77 arc90 293.85,208.93 293.85,205.95 arc-90 292.05,204.15 Q3.2
N$118
  Bottom 1.016: Q2.2 281.15,204.15 arc90 283.69,206.69 283.69,211.77 arc-90 286.23,214.31 298.93,214.31 arc90 R35.1
N$119
  Top 1.016: R38.1 298.93,216.35 arc-90 294.35,211.77 281.38,211.77 arc45 277.52,210.17 274.8,207.45 272.22,204.9 arc-45 270.4,204.15 Q5.2
N$120
  Bottom 1.016: R37.1 267.2,216.85 arc45 258.71,213.34 254.24,208.87 arc45 252.89,205.6 arc90 254.33,204.15 Q4.2
N$121
  Bottom 1.016: S34.4 R37.2
N$122
  Bottom 1.016: S34.3 R38.2
N$123
  Bottom 1.016: S34.2 R35.2
N$124
  Bottom 1.016: S34.1 R36.2
N$125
